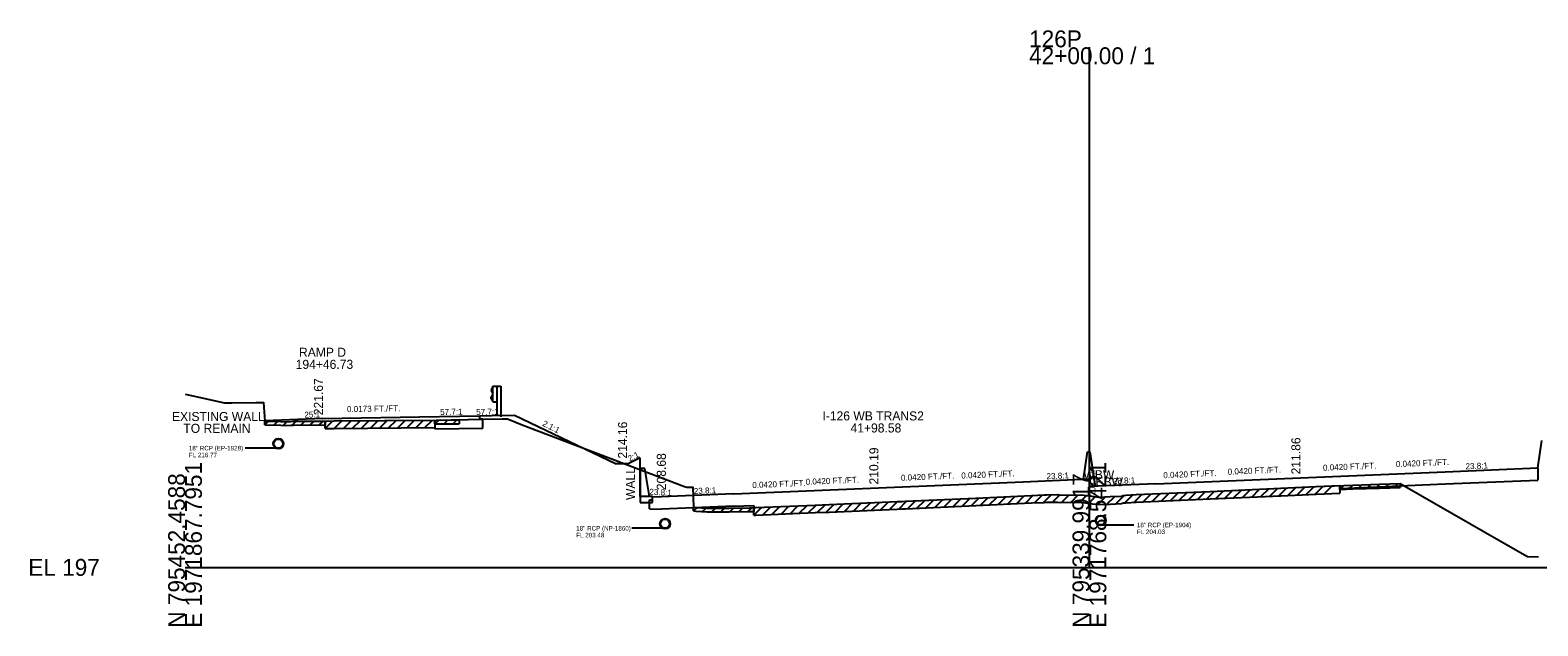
# Model space of a CAD drawing. Extents: x -161 to 1970889, y -4362 to 797231.
# Drawn here: x 974.3 to 1224.4, y 4490.3 to 4589.1 of the extents above; entities that cross this region are included whole.
import ezdxf

# ---------------------------------------------------------------- set-up
doc = ezdxf.new("R2010")
doc.units = 0
for name, color, linetype in [('RD_GPK_XS_Cell', 7, 'Continuous'), ('RD_XS_Base', 7, 'Continuous'), ('RD_XS_Box', 7, 'Continuous'), ('RD_XS_EarthShd', 7, 'Continuous'), ('RD_XS_ExGround', 7, 'Continuous'), ('RD_XS_ExPaveRet', 7, 'Continuous'), ('RD_XS_GR', 7, 'Continuous'), ('RD_XS_MedBWall', 7, 'Continuous'), ('RD_XS_Misc_Line', 7, 'Continuous'), ('RD_XS_Pave', 7, 'Continuous'), ('RD_XS_PaveOvlay', 7, 'Continuous'), ('RD_XS_PaveShd', 7, 'Continuous'), ('RD_XS_Pipe', 7, 'Continuous'), ('RD_XS_TieSlope', 7, 'Continuous'), ('RD_XS_TX_Elev_EX', 7, 'Continuous'), ('RD_XS_TX_Elev_PR', 7, 'Continuous'), ('RD_XS_TX_Misc', 7, 'Continuous'), ('RD_XS_TX_MkPT', 7, 'Continuous'), ('RD_XS_TX_Notes', 7, 'Continuous'), ('RD_XS_TX_Profile', 7, 'Continuous'), ('RD_XS_TX_Slope', 7, 'Continuous'), ('RD_XS_TX_Station', 7, 'Continuous')]:
    doc.layers.add(name, color=color, linetype=linetype)

msp = doc.modelspace()

# ---------------------------------------------------------------- linework, layer by layer
at = {"layer": 'RD_GPK_XS_Cell'}
for p, q in [((1150, 4500), (1150, 4586.24)), ((1000, 4500), (1150, 4500)), ((1150, 4500), (1300, 4500))]:
    msp.add_line(p, q, dxfattribs=at)
at = {"layer": 'RD_XS_Base'}
for p, q in [((1048.91, 4524.56), (1048.91, 4525.12)), ((1049.41, 4524.57), (1048.91, 4524.56)), ((1049.41, 4523.09), (1049.41, 4524.57)), ((1041.45, 4522.95), (1049.41, 4523.09)), ((1209, 4513.83), (1224.38, 4514.48)), ((1077.51, 4511.18), (1077.51, 4511.74)), ((1191.52, 4513.09), (1209, 4513.83)), ((1077.01, 4511.2), (1077.51, 4511.18)), ((1077.01, 4509.72), (1077.01, 4511.2)), ((1077.01, 4509.72), (1079, 4509.64)), ((1091, 4510.14), (1079, 4509.64)), ((1091, 4510.14), (1094.35, 4510.28))]:
    msp.add_line(p, q, dxfattribs=at)
at = {"layer": 'RD_XS_Box'}
for p, q in [((1075.51, 4511.74), (1075.51, 4518.16)), ((1077.51, 4511.74), (1075.51, 4511.74))]:
    msp.add_line(p, q, dxfattribs=at)
at = {"layer": 'RD_XS_EarthShd'}
msp.add_line((1048.91, 4525.12), (1050.91, 4525.16), dxfattribs=at)
at = {"layer": 'RD_XS_ExGround'}
msp.add_lwpolyline([(1000, 4528.75), (1000.77, 4528.56), (1006.55, 4527.28), (1007.77, 4527.29), (1011.8, 4527.36), (1013.01, 4527.36), (1013.25, 4524.27), (1015.87, 4524.18), (1016.73, 4524.16), (1017.57, 4524.18), (1018.01, 4524.23), (1024.71, 4524.28), (1041.64, 4524.44), (1044.2, 4524.45), (1045.46, 4524.45), (1046.98, 4524.5), (1049.51, 4524.6), (1052.58, 4524.64), (1053.5, 4524.64), (1055.89, 4523.62), (1082.85, 4513.43), (1083.25, 4513.28), (1084.25, 4513.28), (1084.35, 4509.98), (1084.74, 4509.95), (1086.58, 4509.83), (1090.24, 4509.82), (1093.62, 4509.89), (1094.69, 4509.91), (1104.49, 4510.33), (1106.83, 4510.42), (1118.09, 4510.91), (1119.02, 4510.95), (1119.48, 4510.97), (1131.15, 4511.49), (1140.41, 4511.93), (1142.49, 4512.03), (1142.93, 4512.04), (1144.79, 4512.06), (1145.19, 4511.99), (1148.68, 4512.04), (1150, 4511.87), (1151.57, 4511.67), (1153.45, 4511.75), (1155.35, 4511.83), (1155.59, 4511.94), (1156.04, 4511.96), (1157.73, 4512.06), (1170.05, 4512.59), (1181.74, 4513.14), (1187.62, 4513.39), (1193.68, 4513.65), (1198.14, 4513.78), (1201.52, 4513.89), (1218.68, 4504.06), (1222.68, 4501.8), (1224.49, 4501.73)], dxfattribs=at)
at = {"layer": 'RD_XS_ExPaveRet'}
for p, q in [((1013.25, 4523.64), (1013.25, 4524.27)), ((1023.26, 4523.02), (1023.26, 4524.27)), ((1023.26, 4524.27), (1023.26, 4523.64)), ((1041.45, 4524.44), (1041.45, 4523.19)), ((1041.45, 4523.82), (1041.45, 4524.44)), ((1045.46, 4524.45), (1045.46, 4523.83)), ((1013.25, 4523.64), (1015.87, 4523.56)), ((1015.87, 4523.56), (1016.73, 4523.53)), ((1016.73, 4523.53), (1017.57, 4523.56)), ((1017.57, 4523.56), (1018.01, 4523.61)), ((1018.01, 4523.61), (1023.26, 4523.64)), ((1023.26, 4523.02), (1024.71, 4523.03)), ((1024.71, 4523.03), (1041.45, 4523.19)), ((1041.45, 4523.82), (1041.64, 4523.82)), ((1041.64, 4523.82), (1044.2, 4523.82)), ((1044.2, 4523.82), (1045.46, 4523.83)), ((1201.52, 4513.89), (1201.52, 4513.26)), ((1170.05, 4511.34), (1181.74, 4511.89)), ((1181.74, 4511.89), (1187.62, 4512.14)), ((1187.62, 4512.14), (1191.52, 4512.31)), ((1191.52, 4513.56), (1191.52, 4512.31)), ((1191.52, 4512.93), (1191.52, 4513.56)), ((1191.52, 4512.93), (1193.68, 4513.02)), ((1193.68, 4513.02), (1198.14, 4513.16)), ((1198.14, 4513.16), (1201.52, 4513.26)), ((1084.35, 4509.36), (1084.35, 4509.98)), ((1084.35, 4509.36), (1084.74, 4509.33)), ((1084.74, 4509.33), (1086.58, 4509.21)), ((1086.58, 4509.21), (1090.24, 4509.19)), ((1090.24, 4509.19), (1093.62, 4509.27)), ((1093.62, 4509.27), (1094.35, 4509.28)), ((1094.35, 4508.66), (1094.35, 4509.91)), ((1094.35, 4509.91), (1094.35, 4509.28)), ((1094.69, 4508.66), (1104.49, 4509.08)), ((1104.49, 4509.08), (1106.83, 4509.17)), ((1106.83, 4509.17), (1118.09, 4509.66)), ((1118.09, 4509.66), (1119.02, 4509.7)), ((1119.02, 4509.7), (1119.48, 4509.72)), ((1119.48, 4509.72), (1131.15, 4510.24)), ((1131.15, 4510.24), (1140.41, 4510.68)), ((1140.41, 4510.68), (1142.49, 4510.78)), ((1142.49, 4510.78), (1142.93, 4510.79)), ((1142.93, 4510.79), (1144.79, 4510.81)), ((1144.79, 4510.81), (1145.19, 4510.74)), ((1145.19, 4510.74), (1148.68, 4510.79)), ((1148.68, 4510.79), (1150, 4510.62)), ((1150, 4510.62), (1151.57, 4510.42)), ((1151.57, 4510.42), (1153.45, 4510.5)), ((1153.45, 4510.5), (1155.35, 4510.58)), ((1155.35, 4510.58), (1155.59, 4510.69)), ((1155.59, 4510.69), (1156.04, 4510.71)), ((1156.04, 4510.71), (1157.73, 4510.81)), ((1157.73, 4510.81), (1170.05, 4511.34)), ((1094.35, 4508.66), (1094.69, 4508.66))]:
    msp.add_line(p, q, dxfattribs=at)
at = {"layer": 'RD_XS_GR'}
for p, q in [((1051.06, 4529.87), (1050.79, 4529.43)), ((1050.79, 4529.43), (1050.79, 4529.32)), ((1050.79, 4529.32), (1051.06, 4528.88)), ((1051.06, 4530.03), (1051.73, 4530.03)), ((1051.06, 4527.46), (1051.06, 4530.03)), ((1051.73, 4530.03), (1052.39, 4530.03)), ((1051.73, 4530.03), (1051.73, 4525.09)), ((1052.39, 4530.03), (1052.39, 4524.98)), ((1050.79, 4528.17), (1051.06, 4528.61)), ((1050.79, 4528.06), (1050.79, 4528.17)), ((1051.06, 4527.62), (1050.79, 4528.06)), ((1051.06, 4527.46), (1051.73, 4527.46))]:
    msp.add_line(p, q, dxfattribs=at)
at = {"layer": 'RD_XS_MedBWall'}
for p, q in [((1149, 4514.62), (1149.67, 4519.16)), ((1149.67, 4519.16), (1150.14, 4519.16)), ((1151, 4513.43), (1150.14, 4519.16)), ((1224.38, 4516.52), (1225.05, 4521.06)), ((1076.26, 4516.4), (1075.51, 4516.4)), ((1075.51, 4516.4), (1075.51, 4510.74)), ((1077.01, 4511.74), (1076.26, 4516.4)), ((1224.38, 4516.52), (1224.38, 4514.48)), ((1077.51, 4511.74), (1077.01, 4511.74)), ((1077.51, 4510.74), (1077.51, 4511.74)), ((1075.51, 4510.74), (1077.51, 4510.74))]:
    msp.add_line(p, q, dxfattribs=at)
at = {"layer": 'RD_XS_Misc_Line'}
for p, q in [((1013.25, 4523.64), (1013.86, 4524.25)), ((1014.75, 4523.59), (1015.36, 4524.2)), ((1016.26, 4523.54), (1016.87, 4524.16)), ((1017.76, 4523.58), (1018.42, 4524.24)), ((1019.26, 4523.62), (1019.89, 4524.25)), ((1020.76, 4523.63), (1021.39, 4524.26)), ((1022.26, 4523.64), (1022.89, 4524.27)), ((1023.26, 4523.02), (1024.52, 4524.28)), ((1024.76, 4523.03), (1026.03, 4524.29)), ((1026.27, 4523.04), (1027.53, 4524.31)), ((1027.77, 4523.06), (1029.03, 4524.32)), ((1029.27, 4523.07), (1030.53, 4524.34)), ((1030.77, 4523.09), (1032.03, 4524.35)), ((1032.27, 4523.1), (1033.53, 4524.36)), ((1033.77, 4523.12), (1035.04, 4524.38)), ((1035.27, 4523.13), (1036.54, 4524.39)), ((1036.78, 4523.15), (1038.04, 4524.41)), ((1038.28, 4523.16), (1039.54, 4524.42)), ((1039.78, 4523.17), (1041.04, 4524.44)), ((1041.45, 4523.82), (1042.08, 4524.44)), ((1042.96, 4523.82), (1043.58, 4524.45)), ((1044.46, 4523.82), (1045.08, 4524.45)), ((1200.53, 4513.23), (1201.18, 4513.88)), ((1127.38, 4510.07), (1128.69, 4511.38)), ((1128.88, 4510.14), (1130.19, 4511.45)), ((1130.38, 4510.21), (1131.69, 4511.52)), ((1131.88, 4510.27), (1133.2, 4511.59)), ((1133.38, 4510.35), (1134.7, 4511.66)), ((1134.88, 4510.42), (1136.2, 4511.73)), ((1136.39, 4510.49), (1137.7, 4511.8)), ((1137.89, 4510.56), (1139.2, 4511.88)), ((1139.39, 4510.63), (1140.7, 4511.95)), ((1140.89, 4510.71), (1142.2, 4512.02)), ((1142.39, 4510.78), (1143.66, 4512.04)), ((1143.89, 4510.8), (1145.1, 4512.01)), ((1145.39, 4510.75), (1146.66, 4512.01)), ((1146.9, 4510.77), (1148.16, 4512.03)), ((1148.4, 4510.79), (1149.54, 4511.93)), ((1149.9, 4510.63), (1151.01, 4511.74)), ((1151.4, 4510.44), (1152.68, 4511.72)), ((1152.9, 4510.48), (1154.21, 4511.78)), ((1154.4, 4510.54), (1155.81, 4511.95)), ((1155.9, 4510.7), (1157.23, 4512.03)), ((1157.41, 4510.79), (1158.72, 4512.1)), ((1158.91, 4510.86), (1160.21, 4512.16)), ((1160.41, 4510.92), (1161.72, 4512.23)), ((1161.91, 4510.99), (1163.22, 4512.29)), ((1163.41, 4511.05), (1164.72, 4512.36)), ((1164.91, 4511.12), (1166.22, 4512.42)), ((1166.41, 4511.18), (1167.72, 4512.49)), ((1167.92, 4511.24), (1169.22, 4512.55)), ((1169.42, 4511.31), (1170.73, 4512.62)), ((1170.92, 4511.38), (1172.23, 4512.69)), ((1172.42, 4511.45), (1173.73, 4512.76)), ((1173.92, 4511.52), (1175.24, 4512.83)), ((1175.42, 4511.59), (1176.74, 4512.9)), ((1176.92, 4511.66), (1178.24, 4512.97)), ((1178.43, 4511.73), (1179.74, 4513.05)), ((1179.93, 4511.8), (1181.24, 4513.12)), ((1181.43, 4511.88), (1182.74, 4513.18)), ((1182.93, 4511.94), (1184.24, 4513.25)), ((1184.43, 4512), (1185.74, 4513.31)), ((1185.93, 4512.07), (1187.24, 4513.37)), ((1187.44, 4512.13), (1188.74, 4513.44)), ((1188.94, 4512.2), (1190.24, 4513.5)), ((1191.52, 4512.93), (1192.18, 4513.59)), ((1193.02, 4513), (1193.68, 4513.65)), ((1194.52, 4513.05), (1195.17, 4513.69)), ((1196.03, 4513.1), (1196.67, 4513.74)), ((1197.53, 4513.14), (1198.17, 4513.78)), ((1199.03, 4513.19), (1199.67, 4513.83)), ((1084.35, 4509.36), (1084.93, 4509.94)), ((1085.85, 4509.25), (1086.43, 4509.84)), ((1087.35, 4509.2), (1087.97, 4509.83)), ((1088.85, 4509.2), (1089.47, 4509.82)), ((1090.35, 4509.2), (1090.99, 4509.84)), ((1091.85, 4509.23), (1092.49, 4509.87)), ((1093.35, 4509.26), (1093.99, 4509.9)), ((1094.35, 4508.66), (1095.64, 4509.95)), ((1095.85, 4508.71), (1097.15, 4510.02)), ((1097.35, 4508.78), (1098.65, 4510.08)), ((1098.85, 4508.84), (1100.16, 4510.14)), ((1100.35, 4508.9), (1101.66, 4510.21)), ((1101.85, 4508.97), (1103.16, 4510.27)), ((1103.35, 4509.03), (1104.66, 4510.33)), ((1104.86, 4509.09), (1106.16, 4510.4)), ((1106.36, 4509.15), (1107.66, 4510.46)), ((1107.86, 4509.22), (1109.17, 4510.52)), ((1109.36, 4509.28), (1110.67, 4510.59)), ((1110.86, 4509.35), (1112.17, 4510.65)), ((1112.36, 4509.41), (1113.67, 4510.72)), ((1113.86, 4509.48), (1115.17, 4510.78)), ((1115.37, 4509.54), (1116.67, 4510.85)), ((1116.87, 4509.61), (1118.17, 4510.91)), ((1118.37, 4509.67), (1119.68, 4510.98)), ((1119.87, 4509.74), (1121.18, 4511.04)), ((1121.37, 4509.8), (1122.68, 4511.11)), ((1122.87, 4509.87), (1124.18, 4511.18)), ((1124.37, 4509.94), (1125.68, 4511.25)), ((1125.88, 4510), (1127.19, 4511.31))]:
    msp.add_line(p, q, dxfattribs=at)
at = {"layer": 'RD_XS_Pave'}
for p, q in [((1022.87, 4524.67), (1038.9, 4524.95)), ((1115, 4513.19), (1139, 4514.2)), ((1161, 4513.85), (1185, 4514.86)), ((1185, 4514.86), (1209, 4515.87)), ((1091, 4512.18), (1115, 4513.19))]:
    msp.add_line(p, q, dxfattribs=at)
at = {"layer": 'RD_XS_PaveOvlay'}
for p, q in [((1023.26, 4524.27), (1024.71, 4524.28)), ((1024.71, 4524.28), (1041.45, 4524.44)), ((1041.45, 4524.44), (1041.45, 4522.95)), ((1119.48, 4510.97), (1131.15, 4511.49)), ((1131.15, 4511.49), (1140.41, 4511.93)), ((1140.41, 4511.93), (1142.49, 4512.03)), ((1142.49, 4512.03), (1142.93, 4512.04)), ((1142.93, 4512.04), (1144.79, 4512.06)), ((1144.79, 4512.06), (1145.19, 4511.99)), ((1145.19, 4511.99), (1148.68, 4512.04)), ((1148.68, 4512.04), (1150, 4511.87)), ((1150, 4511.87), (1151.57, 4511.67)), ((1151.57, 4511.67), (1153.45, 4511.75)), ((1153.45, 4511.75), (1155.35, 4511.83)), ((1155.35, 4511.83), (1155.59, 4511.94)), ((1155.59, 4511.94), (1156.04, 4511.96)), ((1156.04, 4511.96), (1157.73, 4512.06)), ((1157.73, 4512.06), (1170.05, 4512.59)), ((1170.05, 4512.59), (1181.74, 4513.14)), ((1181.74, 4513.14), (1187.62, 4513.39)), ((1187.62, 4513.39), (1191.52, 4513.56)), ((1191.52, 4513.56), (1191.52, 4513.09)), ((1094.35, 4510.28), (1094.35, 4509.91)), ((1094.35, 4509.91), (1094.69, 4509.91)), ((1094.69, 4509.91), (1104.49, 4510.33)), ((1104.49, 4510.33), (1106.83, 4510.42)), ((1106.83, 4510.42), (1118.09, 4510.91)), ((1118.09, 4510.91), (1119.02, 4510.95)), ((1119.02, 4510.95), (1119.48, 4510.97))]:
    msp.add_line(p, q, dxfattribs=at)
msp.add_lwpolyline([(1013.25, 4524.29), (1013.25, 4524.27), (1015.87, 4524.18), (1016.73, 4524.16), (1017.57, 4524.18), (1018.01, 4524.23), (1023.26, 4524.27)], dxfattribs=at)
at = {"layer": 'RD_XS_PaveShd'}
for p, q in [((1022.87, 4524.67), (1013.25, 4524.29)), ((1038.9, 4524.95), (1048.91, 4525.12)), ((1209, 4515.87), (1224.38, 4516.52)), ((1139, 4514.2), (1150, 4514.66)), ((1150, 4513.39), (1150, 4514.66)), ((1161, 4513.85), (1150, 4513.39)), ((1077.51, 4511.74), (1079, 4511.68)), ((1091, 4512.18), (1079, 4511.68))]:
    msp.add_line(p, q, dxfattribs=at)
at = {"layer": 'RD_XS_Pipe'}
for p, q in [((1014.98, 4519.77), (1009.98, 4519.77)), ((1079.12, 4506.48), (1074.12, 4506.48)), ((1152.38, 4507.03), (1157.38, 4507.03))]:
    msp.add_line(p, q, dxfattribs=at)
for centre, radius in [((1015.48, 4520.52), 0.85), ((1015.48, 4520.52), 0.75), ((1079.62, 4507.23), 0.85), ((1079.62, 4507.23), 0.75), ((1151.88, 4507.78), 0.85), ((1151.88, 4507.78), 0.75)]:
    msp.add_circle(centre, radius, dxfattribs=at)
at = {"layer": 'RD_XS_TieSlope'}
for p, q in [((1050.91, 4525.16), (1054.67, 4525.22)), ((1054.67, 4525.22), (1071.51, 4517.16)), ((1073.51, 4517.16), (1071.51, 4517.16)), ((1075.51, 4518.16), (1073.51, 4517.16))]:
    msp.add_line(p, q, dxfattribs=at)

# ---------------------------------------------------------------- texts
at = {"layer": 'RD_GPK_XS_Cell'}
for s, p in [('126P', (1140, 4586.24)), ('42+00.00 / 1', (1140, 4583.44)), ('EL 197', (974, 4498.6))]:
    msp.add_text(s, height=2.8, dxfattribs=at).set_placement(p)
for s, p in [('E 1971867.7951', (1002.8, 4490)), ('E 1971768.5421', (1152.8, 4490)), ('N 795452.4588', (1000, 4490)), ('N 795339.9917', (1150, 4490))]:
    msp.add_text(s, height=2.8, rotation=90, dxfattribs=at).set_placement(p)
at = {"layer": 'RD_XS_Pipe'}
for s, p in [('18" RCP (EP-1928)', (1000.63, 4519.4)), ('FL 216.77', (1000.63, 4518.27)), ('18" RCP (NP-1860)', (1064.88, 4506.11)), ('18" RCP (EP-1904)', (1157.88, 4506.66)), ('FL 203.48', (1064.88, 4504.98)), ('FL 204.03', (1157.88, 4505.53))]:
    msp.add_text(s, height=0.75, dxfattribs=at).set_placement(p)
at = {"layer": 'RD_XS_TX_Elev_EX'}
msp.add_text('208.87', height=1, rotation=90, dxfattribs=at).set_placement((1151, 4511.87))
at = {"layer": 'RD_XS_TX_Elev_PR'}
for s, p in [(' 221.67', (1022.87, 4524.67)), (' 211.86', (1185, 4514.86)), (' 210.19', (1115, 4513.19))]:
    msp.add_text(s, height=1.5, rotation=90, dxfattribs=at).set_placement(p)
at = {"layer": 'RD_XS_TX_Misc'}
for s, p in [('214.16', (1073.32, 4518.04)), ('208.68', (1079.75, 4512.8))]:
    msp.add_text(s, height=1.5, rotation=90, dxfattribs=at).set_placement(p)
at = {"layer": 'RD_XS_TX_MkPT'}
for s, p in [('WBW', (1149, 4514.62)), ('EBW', (1151, 4513.43))]:
    msp.add_text(s, height=1.5, dxfattribs=at).set_placement(p)
at = {"layer": 'RD_XS_TX_Notes'}
for s, p in [('EXISTING WALL', (997.83, 4524.27)), ('TO REMAIN', (999.72, 4522.31))]:
    msp.add_text(s, height=1.5, dxfattribs=at).set_placement(p)
msp.add_text('WALL', height=1.5, rotation=90, dxfattribs=at).set_placement((1074.63, 4511.17))
at = {"layer": 'RD_XS_TX_Profile'}
for s, rotation, p in [('57.7:1', 0.9923, (1042.32, 4525.26)), ('57.7:1', 0.9923, (1048.3, 4525.26)), ('23.8:1', 2.405, (1212.41, 4516.26)), ('23.8:1', 2.405, (1142.91, 4514.61)), ('23.8:1', 2.405, (1153.91, 4513.81)), ('23.8:1', 357.595, (1077, 4512.04)), ('23.8:1', 2.405, (1084.41, 4512.15))]:
    msp.add_text(s, height=1, rotation=rotation, dxfattribs=at).set_placement(p)
at = {"layer": 'RD_XS_TX_Slope'}
for s, rotation, p in [('0.0173 FT./FT.', 0.9923, (1026.87, 4525.74)), ('25:1', 2.2871, (1019.81, 4524.8)), ('2.1:1', 333.4698, (1059.17, 4523.53)), ('2:1', 26.5651, (1073.75, 4517.53)), ('0.0420 FT./FT.', 2.405, (1172.96, 4515.36)), ('0.0420 FT./FT.', 2.405, (1188.77, 4516.02)), ('0.0420 FT./FT.', 2.405, (1200.85, 4516.62)), ('0.0420 FT./FT.', 2.405, (1094.11, 4513.14)), ('0.0420 FT./FT.', 2.405, (1102.96, 4513.68)), ('0.0420 FT./FT.', 2.405, (1118.77, 4514.35)), ('0.0420 FT./FT.', 2.405, (1128.77, 4514.72)), ('0.0420 FT./FT.', 2.405, (1162.28, 4514.78))]:
    msp.add_text(s, height=1, rotation=rotation, dxfattribs=at).set_placement(p)
at = {"layer": 'RD_XS_TX_Station'}
for s, p in [('RAMP D', (1018.9, 4534.92)), ('194+46.73', (1018.35, 4532.92)), ('I-126 WB TRANS2', (1105.72, 4524.37)), ('41+98.58', (1110.38, 4522.37))]:
    msp.add_text(s, height=1.5, dxfattribs=at).set_placement(p)

doc.saveas('drawing.dxf')
